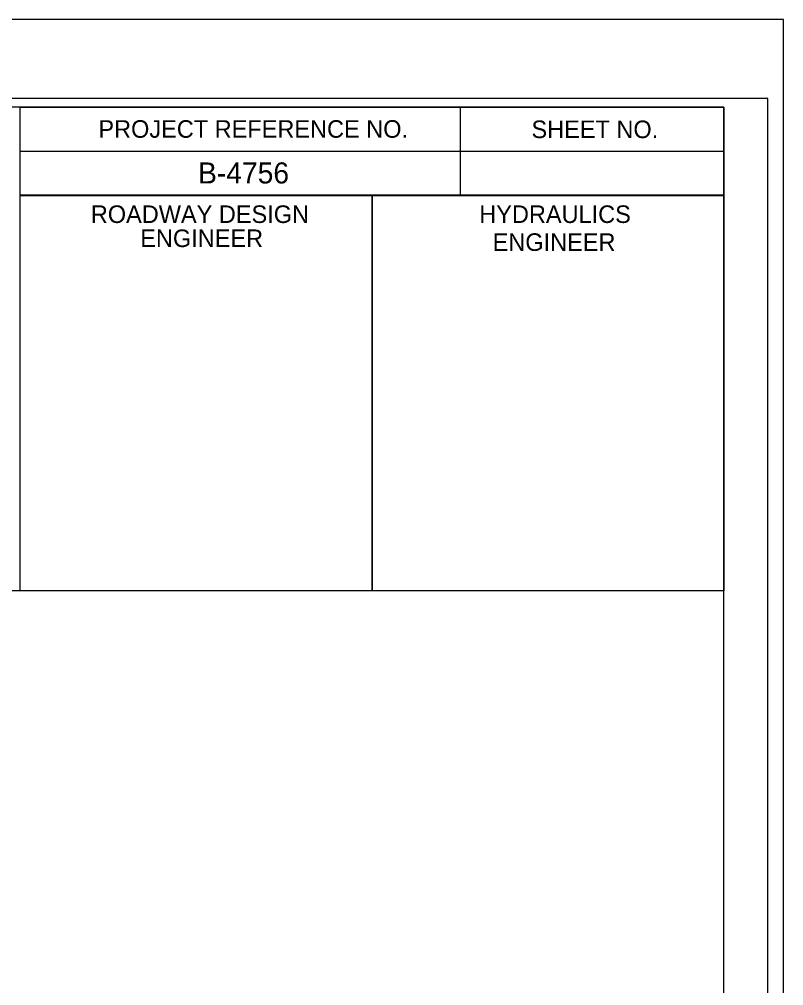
# Model space of a CAD drawing. Extents: x 2431000 to 2534000, y 645879 to 714000.
# Drawn here: x 2465319.4 to 2465536.7, y 677241.9 to 677516.9 of the extents above; entities that cross this region are included whole.
import ezdxf

# ---------------------------------------------------------------- set-up
doc = ezdxf.new("R2010")
doc.units = 0
for name, color, linetype in [('KHA_LOGO', 7, 'Continuous'), ('Old_Level_2', 7, 'Continuous'), ('Prop Dimension', 7, 'Continuous'), ('Prop Terminator CELL', 7, 'Continuous'), ('Sheet Clip Boundary CELL', 7, 'Continuous')]:
    doc.layers.add(name, color=color, linetype=linetype)

msp = doc.modelspace()

# ---------------------------------------------------------------- linework, layer by layer
at = {"layer": 'KHA_LOGO'}
for points in [[(2465319.65, 677466.78), (2465419.7, 677466.78), (2465419.7, 677354.28), (2465319.65, 677354.28)], [(2465419.7, 677466.78), (2465519.7, 677466.78), (2465519.7, 677354.28), (2465419.7, 677354.28)]]:
    msp.add_lwpolyline(points, close=True, dxfattribs=at)
at = {"layer": 'Old_Level_2'}
for p, q in [((2465444.7, 677491.83), (2465444.7, 677466.83)), ((2465319.65, 677479.33), (2465519.7, 677479.33))]:
    msp.add_line(p, q, dxfattribs=at)
for points in [[(2465519.7, 677491.88), (2464019.7, 677491.88), (2464019.7, 676441.88), (2465519.7, 676441.88)], [(2465319.65, 677491.88), (2465519.7, 677491.88), (2465519.7, 677466.83), (2465319.65, 677466.83)]]:
    msp.add_lwpolyline(points, close=True, dxfattribs=at)
at = {"layer": 'Prop Dimension'}
msp.add_lwpolyline([(2463853.2, 676416.88), (2465536.7, 676416.88), (2465536.7, 677516.88), (2463853.2, 677516.88)], close=True, dxfattribs=at)
at = {"layer": 'Prop Terminator CELL'}
msp.add_lwpolyline([(2463866.2, 676439.38), (2465532.2, 676439.38), (2465532.2, 677494.38), (2463866.2, 677494.38)], close=True, dxfattribs=at)
at = {"layer": 'Sheet Clip Boundary CELL'}
msp.add_lwpolyline([(2465219.65, 677354.33), (2465319.65, 677354.33), (2465319.65, 677491.88), (2465219.65, 677491.88)], close=True, dxfattribs=at)

# ---------------------------------------------------------------- texts
at = {"layer": 'KHA_LOGO'}
for s, height, p in [('B-4756', 6, (2465370.19, 677470.17)), ('HYDRAULICS', 5, (2465450.15, 677458.93)), ('ENGINEER', 5, (2465453.95, 677450.98))]:
    msp.add_text(s, height=height, dxfattribs=at).set_placement(p)
at = {"layer": 'Old_Level_2'}
for s, height, p in [('PROJECT REFERENCE NO.', 5.0001, (2465341.85, 677483.18)), ('SHEET NO.', 5, (2465465, 677483.08)), ('ROADWAY DESIGN', 5.0001, (2465339.7, 677458.93)), ('ENGINEER', 5, (2465353.75, 677452.08))]:
    msp.add_text(s, height=height, dxfattribs=at).set_placement(p)

doc.saveas('drawing.dxf')
